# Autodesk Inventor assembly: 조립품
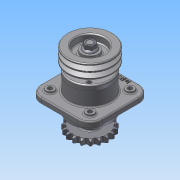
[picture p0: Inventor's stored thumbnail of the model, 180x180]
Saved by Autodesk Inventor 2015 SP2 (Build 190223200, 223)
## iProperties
Created: 2015-07
Part Number: 조립품
Document SubType Name: Assembly
Designer: AMC
Author: AMC
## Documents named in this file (12)
- C:\Users\AMC\Desktop\450735V1017\조립품.iam
- C:\Users\AMC\Desktop\450735V1017\본체.ipt
- C:\Users\AMC\Desktop\450735V1017\2-커버.ipt
- C:\Users\AMC\Desktop\450735V1017\3-축.ipt
- C:\Users\AMC\Desktop\450735V1017\4-V벨트풀리.ipt
- C:\Users\AMC\Desktop\450735V1017\5-체인 스프로킷.ipt
- C:\Users\AMC\Desktop\450735V1017\6-베어링 6206.ipt
- C:\Users\AMC\Desktop\450735V1017\7-부시.ipt
- C:\Users\AMC\Desktop\450735V1017\8-오일실 30x42.ipt
- C:\Users\AMC\Desktop\450735V1017\9-M16-너트.ipt
- C:\Users\AMC\Desktop\450735V1017\10-M6.ipt
- C:\Users\AMC\Desktop\450735V1017\11-키 6x6.ipt
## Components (22 placed, 10 different names)
1. 2-커버:1
2. 3-축:1
3. 4-V벨트풀리:1 — 각도:1
4. 5-체인 스프로킷:1 — 각도:2
5. 6-베어링 6206:1
6. 7-부시:1
7. 8-8-오일실 30x42:1
8. 9-M16 너트:1
9. 11-키 6x6:1 — 각도:1
10. 2-커버:2
11. 6-베어링 6206:2
12. 8-8-오일실 30x42:2
13. 9-M16 너트:2
14. 11-키 6x6:2 — 각도:2
15. 10-M6:1
16. 10-M6:3
17. 10-M6:4
18. 10-M6:5
19. 10-M6:2
20. 10-M6:6
21. 10-M6:7
22. 10-M6:8
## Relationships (2: Angle 2)
- 각도:1 [Angle]: 4-V벨트풀리:1 ↔ 11-키 6x6:1
- 각도:2 [Angle]: 5-체인 스프로킷:1 ↔ 11-키 6x6:2
